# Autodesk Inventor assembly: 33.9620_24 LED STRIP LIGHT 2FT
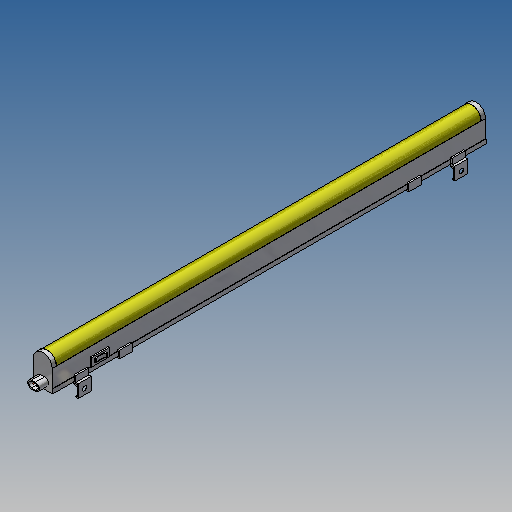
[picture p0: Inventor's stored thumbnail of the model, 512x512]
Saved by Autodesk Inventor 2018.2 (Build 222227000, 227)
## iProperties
Created: 2018-05
Part Number: 33.9620_24 LED STRIP LIGHT 2FT
Document SubType Name: Assembly
Designer: amoles
Author: amoles
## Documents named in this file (4)
- Y:\INVENTOR LIBRARIES\PARTS LIBRARY\WORKSTATION\LIGHTS OUTWATER PLASTICS\33.9620_24 LED STRIP LIGHT 2FT.iam
- Y:\INVENTOR LIBRARIES\PARTS LIBRARY\WORKSTATION\LIGHTS OUTWATER PLASTICS\SUBCOMPONENTS\33.9620_24 LED STRIP LIGHT 2FT.ipt
- Y:\INVENTOR LIBRARIES\PARTS LIBRARY\WORKSTATION\LIGHTS OUTWATER PLASTICS\SUBCOMPONENTS\33.9620 PLASTIC MOUNTING CLIP IN LINE.ipt
- Y:\INVENTOR LIBRARIES\PARTS LIBRARY\WORKSTATION\LIGHTS OUTWATER PLASTICS\SUBCOMPONENTS\33.9620 PLASTIC MOUNTING CLIP OFFSET.ipt
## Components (5 placed, 3 different names)
1. 33.9620_24 LED STRIP LIGHT 2FT:1 — Mate:1, Flush:1, Flush:4, Flush:6, Flush:10, Flush:11, Mate:2, Flush:12, Flush:13
2. 33.9620 PLASTIC MOUNTING CLIP IN LINE:1 — Mate:1, Flush:1, Flush:2, Flush:3, Flush:4, Flush:5, Flush:7
3. 33.9620 PLASTIC MOUNTING CLIP IN LINE:2 — Flush:2, Flush:3, Flush:8, Flush:9, Flush:12
4. 33.9620 PLASTIC MOUNTING CLIP OFFSET:1 — Flush:5, Flush:6, Flush:7
5. 33.9620 PLASTIC MOUNTING CLIP OFFSET:2 — Flush:8, Flush:9, Flush:10
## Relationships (15: Flush 13, Mate 2)
- Mate:1: 33.9620_24 LED STRIP LIGHT 2FT:1 ↔ 33.9620 PLASTIC MOUNTING CLIP IN LINE:1
- Flush:1: 33.9620_24 LED STRIP LIGHT 2FT:1 ↔ 33.9620 PLASTIC MOUNTING CLIP IN LINE:1
- Flush:2: 33.9620 PLASTIC MOUNTING CLIP IN LINE:1 ↔ 33.9620 PLASTIC MOUNTING CLIP IN LINE:2
- Flush:3: 33.9620 PLASTIC MOUNTING CLIP IN LINE:1 ↔ 33.9620 PLASTIC MOUNTING CLIP IN LINE:2
- Flush:4: 33.9620_24 LED STRIP LIGHT 2FT:1 ↔ 33.9620 PLASTIC MOUNTING CLIP IN LINE:1
- Flush:5: 33.9620 PLASTIC MOUNTING CLIP IN LINE:1 ↔ 33.9620 PLASTIC MOUNTING CLIP OFFSET:1
- Flush:6: 33.9620_24 LED STRIP LIGHT 2FT:1 ↔ 33.9620 PLASTIC MOUNTING CLIP OFFSET:1
- Flush:7: 33.9620 PLASTIC MOUNTING CLIP IN LINE:1 ↔ 33.9620 PLASTIC MOUNTING CLIP OFFSET:1
- Flush:8: 33.9620 PLASTIC MOUNTING CLIP IN LINE:2 ↔ 33.9620 PLASTIC MOUNTING CLIP OFFSET:2
- Flush:9: 33.9620 PLASTIC MOUNTING CLIP IN LINE:2 ↔ 33.9620 PLASTIC MOUNTING CLIP OFFSET:2
- Flush:10: 33.9620_24 LED STRIP LIGHT 2FT:1 ↔ 33.9620 PLASTIC MOUNTING CLIP OFFSET:2
- Flush:11: 33.9620_24 LED STRIP LIGHT 2FT:1
- Mate:2: 33.9620_24 LED STRIP LIGHT 2FT:1
- Flush:12: 33.9620_24 LED STRIP LIGHT 2FT:1 ↔ 33.9620 PLASTIC MOUNTING CLIP IN LINE:2
- Flush:13: 33.9620_24 LED STRIP LIGHT 2FT:1
